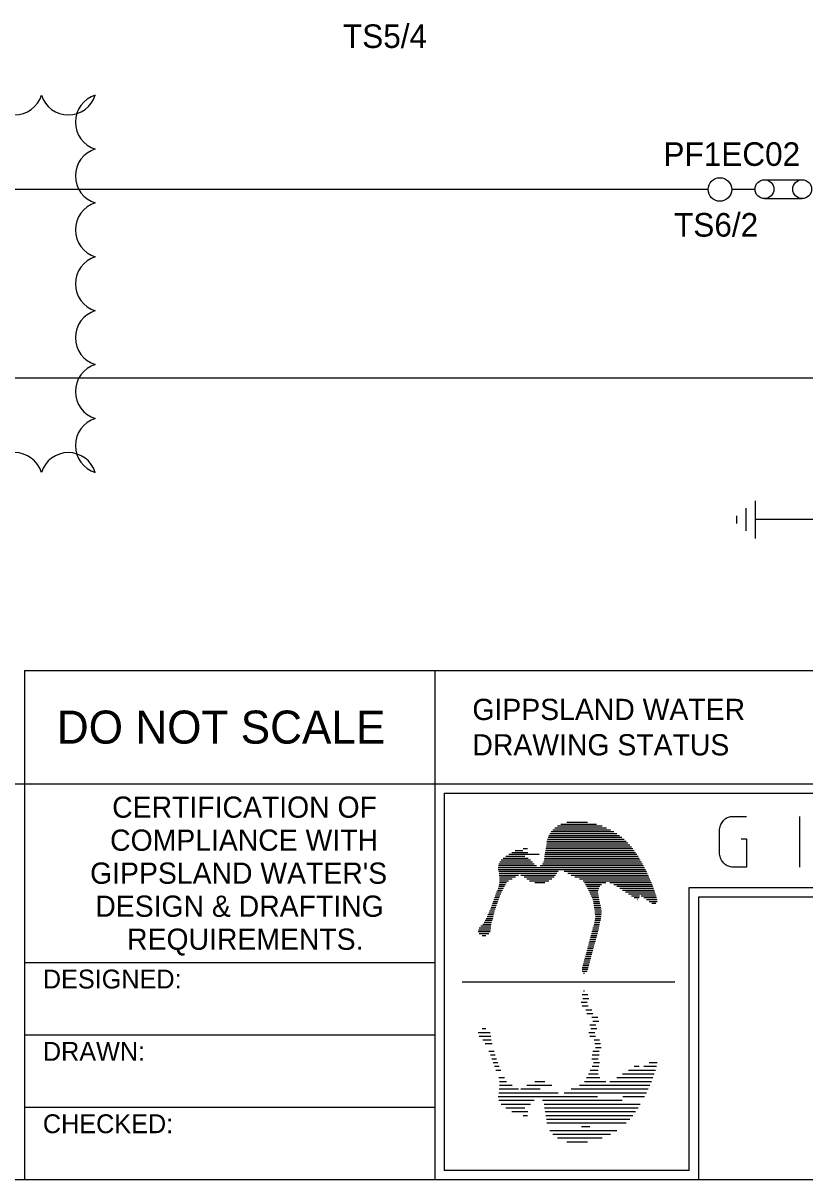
# Model space of a CAD drawing. Extents: x 0 to 841, y 0 to 594.
# Drawn here: x 592.3 to 675.3, y 15 to 137.6 of the extents above; entities that cross this region are included whole.
import ezdxf

# ---------------------------------------------------------------- set-up
doc = ezdxf.new("R2010")
doc.units = 0
for name, color, linetype in [('A1BORDER', 7, 'Continuous'), ('Level 1', 7, 'Continuous'), ('Level 10', 7, 'Continuous')]:
    doc.layers.add(name, color=color, linetype=linetype)

msp = doc.modelspace()

# ---------------------------------------------------------------- linework, layer by layer
at = {"layer": 'A1BORDER'}
for p, q in [((592.5, 69), (592.5, 15)), ((592.5, 69), (829, 69)), ((636, 69), (636, 15)), ((28, 57), (829, 57)), ((637, 56), (788, 56)), ((637, 56), (637, 16)), ((650.01, 52.92), (652.2, 52.92)), ((648.12, 51.52), (655.59, 51.52)), ((648.23, 51.72), (655.31, 51.72)), ((648.37, 51.92), (655, 51.92)), ((648.53, 52.12), (654.64, 52.12)), ((648.74, 52.32), (654.24, 52.32)), ((649.02, 52.52), (653.76, 52.52)), ((649.39, 52.72), (653.15, 52.72)), ((647.81, 50.32), (656.86, 50.32)), ((647.85, 50.52), (656.69, 50.52)), ((647.88, 50.72), (656.5, 50.72)), ((647.91, 50.92), (656.3, 50.92)), ((647.96, 51.12), (656.08, 51.12)), ((648.03, 51.32), (655.85, 51.32)), ((643.26, 49.12), (645.9, 49.12)), ((643.54, 49.32), (645.57, 49.32)), ((643.85, 49.52), (647.09, 49.52)), ((644.18, 49.72), (645.89, 49.72)), ((644.54, 49.92), (645.36, 49.92)), ((645.37, 50.12), (645.86, 50.12)), ((647.63, 49.12), (657.68, 49.12)), ((647.66, 49.32), (657.57, 49.32)), ((647.69, 49.52), (657.44, 49.52)), ((647.71, 49.72), (657.31, 49.72)), ((647.75, 49.92), (657.17, 49.92)), ((647.78, 50.12), (657.02, 50.12)), ((642.73, 48.12), (658.25, 48.12)), ((642.74, 47.92), (658.35, 47.92)), ((642.75, 48.32), (646.79, 48.32)), ((642.81, 48.52), (646.55, 48.52)), ((642.9, 48.72), (646.37, 48.72)), ((643.04, 48.92), (646.16, 48.92)), ((647.19, 48.32), (658.14, 48.32)), ((647.42, 48.52), (658.03, 48.52)), ((647.54, 48.72), (657.92, 48.72)), ((647.61, 48.92), (657.8, 48.92)), ((642.79, 47.72), (649.08, 47.72)), ((642.83, 47.52), (648.95, 47.52)), ((642.85, 47.31), (644.88, 47.31)), ((642.87, 47.12), (644.57, 47.12)), ((642.88, 46.92), (644.23, 46.92)), ((642.88, 46.72), (643.83, 46.72)), ((645.14, 47.31), (648.83, 47.31)), ((645.49, 47.12), (648.67, 47.12)), ((645.76, 46.92), (648.42, 46.92)), ((646.05, 46.72), (648.11, 46.72)), ((649.72, 47.72), (658.45, 47.72)), ((650.12, 47.52), (658.55, 47.52)), ((650.48, 47.31), (658.64, 47.31)), ((650.87, 47.12), (658.73, 47.12)), ((651.36, 46.92), (658.82, 46.92)), ((651.76, 46.72), (658.9, 46.72)), ((642.57, 45.52), (643.1, 45.52)), ((642.65, 45.72), (643.2, 45.72)), ((642.72, 45.92), (643.3, 45.92)), ((642.79, 46.12), (643.4, 46.12)), ((642.84, 46.32), (643.5, 46.32)), ((642.87, 46.52), (643.6, 46.52)), ((646.62, 46.52), (647.67, 46.52)), ((651.88, 46.52), (654.15, 46.52)), ((651.99, 46.32), (653.71, 46.32)), ((652.1, 46.12), (653.52, 46.12)), ((652.2, 45.92), (653.4, 45.92)), ((652.31, 45.72), (653.33, 45.72)), ((652.41, 45.52), (653.31, 45.52)), ((654.57, 46.52), (658.99, 46.52)), ((655, 46.32), (659.07, 46.32)), ((655.31, 46.12), (659.14, 46.12)), ((655.62, 45.92), (659.22, 45.92)), ((655.93, 45.72), (659.29, 45.72)), ((656.24, 45.52), (659.35, 45.52)), ((663, 46), (788, 46)), ((663, 16), (663, 46)), ((642.13, 44.32), (642.62, 44.32)), ((642.21, 44.52), (642.69, 44.52)), ((642.28, 44.72), (642.76, 44.72)), ((642.35, 44.92), (642.83, 44.92)), ((642.43, 45.12), (642.9, 45.12)), ((642.5, 45.32), (643, 45.32)), ((652.5, 45.32), (653.34, 45.32)), ((652.6, 45.12), (653.38, 45.12)), ((652.69, 44.92), (653.41, 44.92)), ((652.78, 44.72), (653.44, 44.72)), ((652.83, 44.52), (653.48, 44.52)), ((652.86, 44.32), (653.53, 44.32)), ((656.55, 45.32), (659.42, 45.32)), ((656.86, 45.12), (657.74, 45.12)), ((657.17, 44.92), (657.68, 44.92)), ((657.51, 44.72), (657.54, 44.72)), ((657.91, 45.12), (659.48, 45.12)), ((658.19, 44.92), (659.54, 44.92)), ((658.47, 44.72), (659.59, 44.72)), ((658.75, 44.52), (659.58, 44.52)), ((659.02, 44.32), (659.47, 44.32)), ((664, 45), (829, 45)), ((664, 15), (664, 45)), ((641.64, 43.12), (642.25, 43.12)), ((641.73, 43.32), (642.3, 43.32)), ((641.82, 43.51), (642.35, 43.51)), ((641.91, 43.72), (642.41, 43.72)), ((641.99, 43.92), (642.48, 43.92)), ((642.06, 44.12), (642.55, 44.12)), ((652.89, 44.12), (653.57, 44.12)), ((652.91, 43.92), (653.62, 43.92)), ((652.94, 43.72), (653.67, 43.72)), ((652.97, 43.51), (653.71, 43.51)), ((653, 43.32), (653.69, 43.32)), ((653.02, 43.12), (653.67, 43.12)), ((640.73, 41.72), (641.95, 41.72)), ((640.9, 41.92), (641.97, 41.92)), ((641.1, 42.12), (642, 42.12)), ((641.25, 42.31), (642.04, 42.31)), ((641.37, 42.52), (642.09, 42.52)), ((641.46, 42.72), (642.15, 42.72)), ((641.55, 42.92), (642.2, 42.92)), ((652.79, 41.72), (653.41, 41.72)), ((652.85, 41.92), (653.45, 41.92)), ((652.9, 42.12), (653.49, 42.12)), ((652.95, 42.31), (653.53, 42.31)), ((652.99, 42.52), (653.57, 42.52)), ((653.03, 42.72), (653.61, 42.72)), ((653.05, 42.92), (653.64, 42.92)), ((640.62, 41.32), (641.88, 41.32)), ((640.63, 41.52), (641.93, 41.52)), ((640.72, 41.12), (641.73, 41.12)), ((641.03, 40.92), (641.43, 40.92)), ((652.47, 40.52), (653.1, 40.52)), ((652.52, 40.72), (653.15, 40.72)), ((652.57, 40.92), (653.2, 40.92)), ((652.63, 41.12), (653.26, 41.12)), ((652.68, 41.32), (653.31, 41.32)), ((652.74, 41.52), (653.37, 41.52)), ((652.14, 39.32), (652.77, 39.32)), ((652.2, 39.52), (652.82, 39.52)), ((652.25, 39.72), (652.88, 39.72)), ((652.3, 39.92), (652.93, 39.92)), ((652.36, 40.12), (652.99, 40.12)), ((652.41, 40.32), (653.04, 40.32)), ((651.82, 38.12), (652.44, 38.12)), ((651.87, 38.32), (652.5, 38.32)), ((651.92, 38.52), (652.55, 38.52)), ((651.98, 38.72), (652.61, 38.72)), ((652.03, 38.92), (652.66, 38.92)), ((652.09, 39.12), (652.72, 39.12)), ((636, 38), (592.5, 38)), ((651.63, 37.32), (652.23, 37.32)), ((651.64, 37.12), (652.17, 37.12)), ((651.65, 37.52), (652.28, 37.52)), ((651.71, 37.72), (652.34, 37.72)), ((651.76, 37.92), (652.39, 37.92)), ((651.79, 36.92), (651.9, 36.92)), ((638.93, 35.98), (661.47, 35.98)), ((651.63, 34.64), (652.23, 34.64)), ((651.79, 35.04), (651.9, 35.04)), ((651.54, 33.84), (652.17, 33.84)), ((651.65, 33.44), (652.28, 33.44)), ((651.71, 34.24), (652.34, 34.24)), ((652.03, 33.04), (652.66, 33.04)), ((652.14, 32.64), (652.77, 32.64)), ((652.66, 32.24), (653.29, 32.24)), ((641.03, 31.04), (641.43, 31.04)), ((652.47, 31.44), (653.1, 31.44)), ((652.57, 31.04), (653.2, 31.04)), ((652.77, 31.84), (653.4, 31.84)), ((636, 30.34), (592.5, 30.34)), ((640.62, 30.64), (641.88, 30.64)), ((640.73, 30.24), (641.95, 30.24)), ((641.1, 29.84), (642, 29.84)), ((641.37, 29.44), (642.09, 29.44)), ((652.34, 30.64), (652.97, 30.64)), ((652.45, 30.24), (653.07, 30.24)), ((652.9, 29.84), (653.49, 29.84)), ((652.99, 29.44), (653.57, 29.44)), ((641.73, 28.64), (642.3, 28.64)), ((641.91, 28.24), (642.41, 28.24)), ((652.72, 28.24), (653.44, 28.24)), ((652.77, 28.64), (653.46, 28.64)), ((653.05, 29.04), (653.64, 29.04)), ((642.06, 27.84), (642.55, 27.84)), ((642.21, 27.44), (642.69, 27.44)), ((642.35, 27.04), (642.83, 27.04)), ((652.66, 27.84), (653.35, 27.84)), ((652.69, 27.04), (653.41, 27.04)), ((652.83, 27.44), (653.48, 27.44)), ((657.17, 27.04), (657.68, 27.04)), ((658.19, 27.04), (659.54, 27.04)), ((658.75, 27.44), (659.58, 27.44)), ((642.5, 26.64), (643, 26.64)), ((642.79, 25.84), (643.4, 25.84)), ((652.1, 25.84), (653.52, 25.84)), ((652.31, 26.24), (653.33, 26.24)), ((652.5, 26.64), (653.34, 26.64)), ((655.31, 25.84), (659.14, 25.84)), ((655.93, 26.24), (659.29, 26.24)), ((656.55, 26.64), (659.42, 26.64)), ((642.85, 24.65), (644.88, 24.65)), ((642.87, 25.44), (643.6, 25.44)), ((642.88, 25.04), (644.23, 25.04)), ((645.14, 24.65), (647.18, 24.65)), ((645.76, 25.04), (648.42, 25.04)), ((646.62, 25.44), (647.67, 25.44)), ((650.48, 24.65), (658.64, 24.65)), ((651.36, 25.04), (658.82, 25.04)), ((651.88, 25.44), (654.15, 25.44)), ((654.57, 25.44), (658.99, 25.44)), ((642.73, 23.84), (653.27, 23.84)), ((642.79, 24.24), (649.08, 24.24)), ((642.81, 23.44), (646.55, 23.44)), ((647.42, 23.44), (655.89, 23.44)), ((649.72, 24.24), (658.45, 24.24)), ((655.94, 23.84), (658.25, 23.84)), ((636, 22.67), (592.5, 22.67)), ((643.04, 23.04), (646.16, 23.04)), ((643.54, 22.64), (645.57, 22.64)), ((644.18, 22.24), (645.89, 22.24)), ((647.61, 23.04), (657.8, 23.04)), ((647.66, 22.64), (657.57, 22.64)), ((647.71, 22.24), (657.31, 22.24)), ((645.37, 21.84), (645.86, 21.84)), ((647.78, 21.84), (657.02, 21.84)), ((647.85, 21.44), (656.69, 21.44)), ((647.91, 21.04), (656.3, 21.04)), ((648.23, 20.24), (655.31, 20.24)), ((648.53, 19.84), (654.64, 19.84)), ((651.57, 20.64), (652.44, 20.64)), ((649.02, 19.44), (653.76, 19.44)), ((650.01, 19.04), (652.2, 19.04)), ((663, 16), (637, 16)), ((829, 15), (28, 15))]:
    msp.add_line(p, q, dxfattribs=at)
for points in [[(668.49, 51.15), (669.06, 51.15), (669.06, 48.16), (667.64, 48.16), (667.51, 48.16), (667.39, 48.18), (667.28, 48.21), (667.15, 48.25), (667.04, 48.3), (666.93, 48.36), (666.82, 48.43), (666.73, 48.51), (666.64, 48.6), (666.55, 48.7), (666.48, 48.8), (666.41, 48.91), (666.35, 49.02), (666.31, 49.14), (666.27, 49.27), (666.24, 49.39), (666.22, 49.52), (666.22, 49.66), (666.22, 52.05), (666.22, 52.18), (666.24, 52.31), (666.27, 52.43), (666.31, 52.56), (666.35, 52.67), (666.41, 52.79), (666.48, 52.9), (666.55, 53), (666.64, 53.1), (666.73, 53.19), (666.82, 53.27), (666.93, 53.34), (667.04, 53.4), (667.15, 53.45), (667.28, 53.49), (667.39, 53.52), (667.51, 53.54), (667.64, 53.54), (669.06, 53.54)], [(674.74, 48.16), (674.74, 53.54)]]:
    msp.add_lwpolyline(points, dxfattribs=at)
at = {"layer": 'Level 1'}
for p, q in [((670.98, 121.03), (674.98, 121.03)), ((665, 120), (540, 120)), ((670, 120), (667.5, 120)), ((670.98, 119.03), (674.98, 119.03)), ((680, 100), (540, 100)), ((680, 85), (670, 85))]:
    msp.add_line(p, q, dxfattribs=at)
for centre in [(670.98, 120.03), (674.98, 120.03)]:
    msp.add_circle(centre, 1, dxfattribs=at)
for centre, start, end in [((591.43, 130.9), 197.5, 342.5), ((597.14, 130.9), 197.5, 342.5), ((600.9, 127.14), 107.5, 252.5), ((600.9, 121.43), 107.5, 252.5), ((600.9, 115.71), 107.5, 252.5), ((600.9, 110), 107.5, 252.5), ((600.9, 104.29), 107.5, 252.5), ((600.9, 98.57), 107.5, 252.5), ((600.9, 92.86), 107.5, 252.5), ((591.43, 89.1), 17.5, 162.5), ((597.14, 89.1), 17.5, 162.5)]:
    msp.add_arc(centre, 3, start, end, dxfattribs=at)
at = {"layer": 'Level 10'}
for p, q in [((669, 86.2), (669, 83.8)), ((670, 87), (670, 83)), ((668, 85.4), (668, 84.6))]:
    msp.add_line(p, q, dxfattribs=at)
msp.add_circle((666.25, 120), 1.25, dxfattribs=at)

# ---------------------------------------------------------------- texts
at = {"layer": 'A1BORDER'}
for s, height, p in [('GIPPSLAND WATER', 2.25, (640, 63.75)), ('DO NOT SCALE', 3.5, (595.92, 61.25)), ('DRAWING STATUS', 2.25, (640, 60)), ('CERTIFICATION OF', 2.25, (601.79, 53.39)), ('COMPLIANCE WITH', 2.25, (601.57, 49.89)), ("GIPPSLAND WATER'S", 2.25, (599.45, 46.39)), ('DESIGN & DRAFTING', 2.25, (600, 42.89)), ('REQUIREMENTS.', 2.25, (603.37, 39.39)), ('DESIGNED:', 2, (594.44, 35.29)), ('DRAWN:', 2, (594.44, 27.62)), ('CHECKED:', 2, (594.44, 19.95))]:
    msp.add_text(s, height=height, dxfattribs=at).set_placement(p)
at = {"layer": 'Level 1'}
for s, p in [('TS5/4', (626.27, 135)), ('PF1EC02', (660.27, 122.5)), ('TS6/2', (661.39, 115))]:
    msp.add_text(s, height=2.5, dxfattribs=at).set_placement(p)

doc.saveas('drawing.dxf')
